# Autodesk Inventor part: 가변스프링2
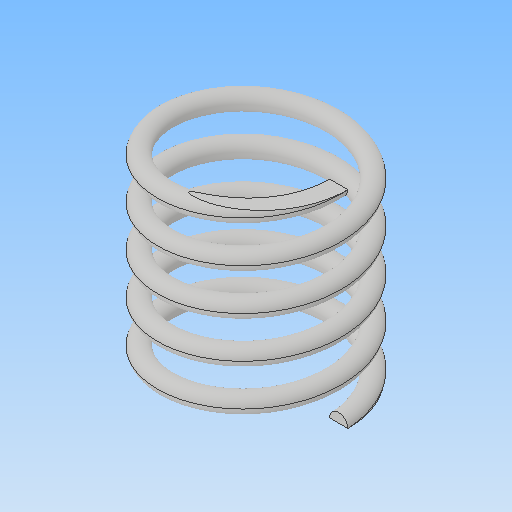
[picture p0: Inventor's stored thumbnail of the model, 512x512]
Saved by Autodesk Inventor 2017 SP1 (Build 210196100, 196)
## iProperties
Part Number: 가변스프링2
Material: 일반
Document SubType Name: Modeling
Designer: MRC
Density: 1 g/cm^3
Appearance: 기본값
Mass: 0.872289 g
Surface Area: 17.713 cm^2
Volume: 0.872289 cm^3
Author: MRC
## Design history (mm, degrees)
sketch "스케치1"
  geometry: L1 (0, 0)-(0, 22.5); L2 (0, 0)-(9, 0); L3 (0, 22.5)-(9, 22.5); C1 r 1 at (9, 0)
  constraints: 6 end point, 1 centre point, 1 coincident, 1 parallel, 1 perpendicular, 1 vertical
  dimensions: "d0" = 22.5 distance of L1.start L1.end (derived); "d1" = 9 distance of L1.start L2.end; "d2" = 9 distance of L1.end L3.end; "d3" = 2 diameter of C1
feature "코일1" sketch "스케치1" pitch "d4" = 10; turns "d6" = 5; dims "d5" = 22.5 (= d0), "d7" = 0, angle "d8" = 90 deg, angle "d9" = 90 deg, "d10" = 0, "d11" = 0
sketch "스케치2"
  geometry: L1 (22.5, 20)-(0, 20); L2 (0, 20)-(0, -20); L3 (0, -20)-(22.5, -20); L4 (22.5, -20)-(22.5, 20); 2 further points
  constraints: 8 end point, 2 parallel, 1 coincident, 1 horizontal, 1 midpoint, 1 perpendicular
  dimensions: "d12" = 40 distance of L3.end L1.start; "d13" = 22.5 distance of L2.end L3.end (= d0)
extrude "돌출1" sketch "스케치2" stored distance "d14" = 0; taper "d15" = 0 deg
node "솔리드1"
